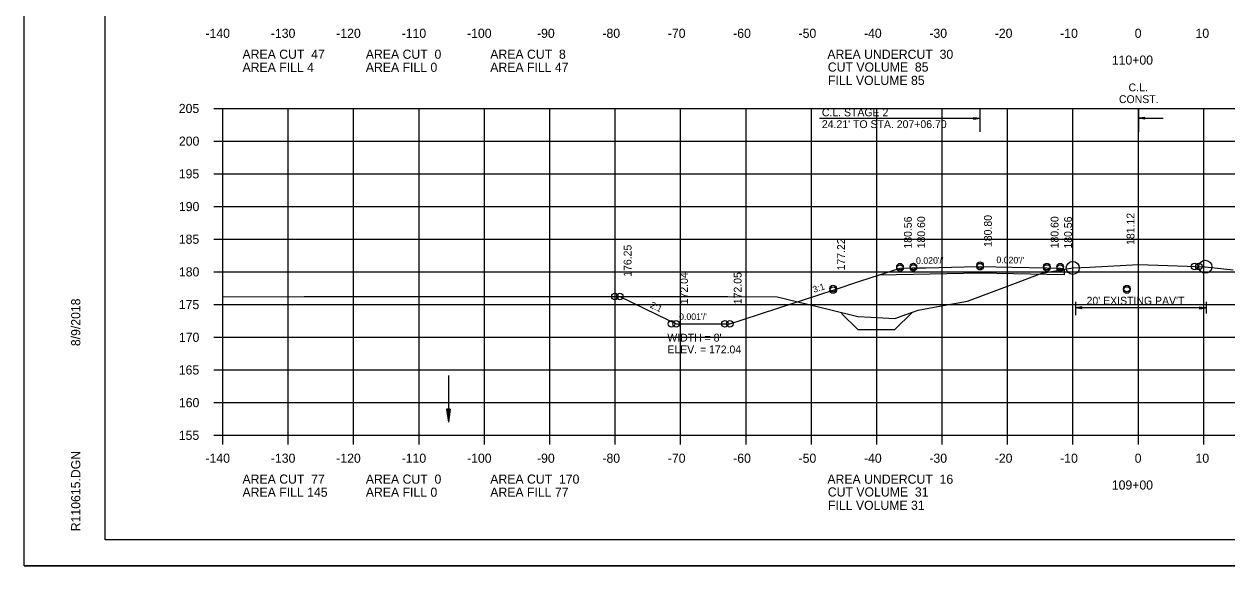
# Model space of a CAD drawing. Extents: x 1372132 to 1372465, y 380083 to 381790.
# Drawn here: x 1372131.6 to 1372315.6, y 381363.5 to 381446.4 of the extents above; entities that cross this region are included whole.
import ezdxf

# ---------------------------------------------------------------- set-up
doc = ezdxf.new("R2010")
doc.units = 0
for name, color, linetype in [('R_Alt Surface', 7, 'Continuous'), ('R_Axis', 7, 'Continuous'), ('R_Axis Annot', 7, 'Continuous'), ('R_Border', 7, 'Continuous'), ('R_Dimension', 7, 'Continuous'), ('R_Draft', 7, 'Continuous'), ('R_Erosion', 7, 'Continuous'), ('R_Exist Surface', 7, 'Continuous'), ('R_Fin Surface', 7, 'Continuous'), ('R_Grid', 7, 'Continuous'), ('R_No Plot', 7, 'Continuous'), ('R_Xsect Elev', 7, 'Continuous'), ('R_Xsect Slope', 7, 'Continuous')]:
    doc.layers.add(name, color=color, linetype=linetype)

msp = doc.modelspace()

# ---------------------------------------------------------------- linework, layer by layer
at = {"layer": 'R_Alt Surface'}
msp.add_lwpolyline([(1372290.64, 381408.05), (1372288, 381408.1), (1372277.8, 381408.3), (1372267.6, 381408.1), (1372262.3, 381407.99)], dxfattribs=at)
at = {"layer": 'R_Axis'}
for p, q in [((1372160.61, 381433.5), (1372162.01, 381433.5)), ((1372162.01, 381383.5), (1372162.01, 381433.5)), ((1372160.61, 381428.5), (1372162.01, 381428.5)), ((1372160.61, 381423.5), (1372162.01, 381423.5)), ((1372160.61, 381418.5), (1372162.01, 381418.5)), ((1372160.61, 381413.5), (1372162.01, 381413.5)), ((1372160.61, 381408.5), (1372162.01, 381408.5)), ((1372160.61, 381403.5), (1372162.01, 381403.5)), ((1372160.61, 381398.5), (1372162.01, 381398.5)), ((1372160.61, 381393.5), (1372162.01, 381393.5)), ((1372160.61, 381388.5), (1372162.01, 381388.5)), ((1372160.61, 381383.5), (1372162.01, 381383.5)), ((1372162.01, 381383.5), (1372442.01, 381383.5)), ((1372162.01, 381382.1), (1372162.01, 381383.5)), ((1372172.01, 381382.1), (1372172.01, 381383.5)), ((1372182.01, 381382.1), (1372182.01, 381383.5)), ((1372192.01, 381382.1), (1372192.01, 381383.5)), ((1372202.01, 381382.1), (1372202.01, 381383.5)), ((1372212.01, 381382.1), (1372212.01, 381383.5)), ((1372222.01, 381382.1), (1372222.01, 381383.5)), ((1372232.01, 381382.1), (1372232.01, 381383.5)), ((1372242.01, 381382.1), (1372242.01, 381383.5)), ((1372252.01, 381382.1), (1372252.01, 381383.5)), ((1372262.01, 381382.1), (1372262.01, 381383.5)), ((1372272.01, 381382.1), (1372272.01, 381383.5)), ((1372282.01, 381382.1), (1372282.01, 381383.5)), ((1372292.01, 381382.1), (1372292.01, 381383.5)), ((1372302.01, 381382.1), (1372302.01, 381383.5)), ((1372312.01, 381382.1), (1372312.01, 381383.5))]:
    msp.add_line(p, q, dxfattribs=at)
at = {"layer": 'R_Border'}
for p, q in [((1372144.01, 381367.5), (1372144.01, 381572.96)), ((1372144.01, 381367.5), (1372144.01, 381367.5)), ((1372460.19, 381367.5), (1372144.01, 381367.5))]:
    msp.add_line(p, q, dxfattribs=at)
at = {"layer": 'R_Dimension'}
for p, q in [((1372196.19, 381387.52), (1372196.49, 381385.52)), ((1372196.79, 381387.52), (1372196.19, 381387.52)), ((1372196.19, 381387.52), (1372196.49, 381385.52)), ((1372196.79, 381387.52), (1372196.19, 381387.52)), ((1372196.24, 381387.52), (1372196.49, 381385.86)), ((1372196.24, 381387.52), (1372196.49, 381385.86)), ((1372196.29, 381387.52), (1372196.49, 381386.2)), ((1372196.29, 381387.52), (1372196.49, 381386.2)), ((1372196.34, 381387.52), (1372196.49, 381386.54)), ((1372196.34, 381387.52), (1372196.49, 381386.54)), ((1372196.39, 381387.52), (1372196.49, 381386.87)), ((1372196.39, 381387.52), (1372196.49, 381386.87)), ((1372196.44, 381387.52), (1372196.49, 381387.21)), ((1372196.44, 381387.52), (1372196.49, 381387.21)), ((1372196.79, 381387.52), (1372196.49, 381385.52)), ((1372196.59, 381387.52), (1372196.49, 381386.87)), ((1372196.69, 381387.52), (1372196.49, 381386.2)), ((1372196.74, 381387.52), (1372196.49, 381385.86)), ((1372196.64, 381387.52), (1372196.49, 381386.54)), ((1372196.54, 381387.52), (1372196.49, 381387.21)), ((1372196.79, 381387.52), (1372196.49, 381385.52)), ((1372196.59, 381387.52), (1372196.49, 381386.87)), ((1372196.69, 381387.52), (1372196.49, 381386.2)), ((1372196.74, 381387.52), (1372196.49, 381385.86)), ((1372196.64, 381387.52), (1372196.49, 381386.54)), ((1372196.54, 381387.52), (1372196.49, 381387.21))]:
    msp.add_line(p, q, dxfattribs=at)
at = {"layer": 'R_Draft'}
for p, q in [((1372277.8, 381429.91), (1372277.8, 381433.5)), ((1372302.01, 381433.5), (1372302.01, 381429.91)), ((1372253.27, 381431.99), (1372277.8, 381431.99)), ((1372276.8, 381432.14), (1372277.8, 381431.99)), ((1372276.8, 381432.14), (1372276.8, 381431.84)), ((1372276.8, 381432.14), (1372277.8, 381431.99)), ((1372276.8, 381432.14), (1372276.8, 381431.84)), ((1372276.8, 381432.11), (1372277.63, 381431.99)), ((1372276.8, 381432.11), (1372277.63, 381431.99)), ((1372276.8, 381432.09), (1372277.46, 381431.99)), ((1372276.8, 381432.09), (1372277.46, 381431.99)), ((1372276.8, 381432.06), (1372277.3, 381431.99)), ((1372276.8, 381432.06), (1372277.3, 381431.99)), ((1372276.8, 381432.04), (1372277.13, 381431.99)), ((1372276.8, 381432.04), (1372277.13, 381431.99)), ((1372276.8, 381432.01), (1372276.96, 381431.99)), ((1372276.8, 381432.01), (1372276.96, 381431.99)), ((1372276.8, 381431.84), (1372277.8, 381431.99)), ((1372276.8, 381431.94), (1372277.13, 381431.99)), ((1372276.8, 381431.89), (1372277.46, 381431.99)), ((1372276.8, 381431.86), (1372277.63, 381431.99)), ((1372276.8, 381431.92), (1372277.3, 381431.99)), ((1372276.8, 381431.97), (1372276.96, 381431.99)), ((1372276.8, 381431.84), (1372277.8, 381431.99)), ((1372276.8, 381431.94), (1372277.13, 381431.99)), ((1372276.8, 381431.89), (1372277.46, 381431.99)), ((1372276.8, 381431.86), (1372277.63, 381431.99)), ((1372276.8, 381431.92), (1372277.3, 381431.99)), ((1372276.8, 381431.97), (1372276.96, 381431.99)), ((1372303.01, 381432.14), (1372302.01, 381431.99)), ((1372302.01, 381431.99), (1372305.82, 381431.99)), ((1372303.01, 381431.84), (1372302.01, 381431.99)), ((1372303.01, 381432.11), (1372302.18, 381431.99)), ((1372303.01, 381431.86), (1372302.18, 381431.99)), ((1372303.01, 381432.09), (1372302.35, 381431.99)), ((1372303.01, 381431.89), (1372302.35, 381431.99)), ((1372303.01, 381432.06), (1372302.52, 381431.99)), ((1372303.01, 381431.92), (1372302.52, 381431.99)), ((1372303.01, 381432.04), (1372302.69, 381431.99)), ((1372303.01, 381431.94), (1372302.69, 381431.99)), ((1372303.01, 381432.01), (1372302.86, 381431.99)), ((1372303.01, 381431.97), (1372302.86, 381431.99)), ((1372303.01, 381431.84), (1372303.01, 381432.14)), ((1372290.64, 381408.87), (1372290.64, 381408.05)), ((1372292.39, 381403.9), (1372292.39, 381401.88)), ((1372293.39, 381403.13), (1372292.39, 381402.98)), ((1372293.39, 381403.13), (1372292.39, 381402.98)), ((1372312.37, 381402.98), (1372292.39, 381402.98)), ((1372293.39, 381402.83), (1372292.39, 381402.98)), ((1372293.39, 381402.83), (1372292.39, 381402.98)), ((1372292.39, 381402.12), (1372292.39, 381402.12)), ((1372293.39, 381403.1), (1372292.56, 381402.98)), ((1372293.39, 381403.1), (1372292.56, 381402.98)), ((1372293.39, 381402.85), (1372292.56, 381402.98)), ((1372293.39, 381402.85), (1372292.56, 381402.98)), ((1372293.39, 381403.08), (1372292.73, 381402.98)), ((1372293.39, 381403.08), (1372292.73, 381402.98)), ((1372293.39, 381402.88), (1372292.73, 381402.98)), ((1372293.39, 381402.88), (1372292.73, 381402.98)), ((1372293.39, 381403.05), (1372292.9, 381402.98)), ((1372293.39, 381403.05), (1372292.9, 381402.98)), ((1372293.39, 381402.91), (1372292.9, 381402.98)), ((1372293.39, 381402.91), (1372292.9, 381402.98)), ((1372293.39, 381403.03), (1372293.07, 381402.98)), ((1372293.39, 381403.03), (1372293.07, 381402.98)), ((1372293.39, 381402.93), (1372293.07, 381402.98)), ((1372293.39, 381402.93), (1372293.07, 381402.98)), ((1372293.39, 381403), (1372293.23, 381402.98)), ((1372293.39, 381403), (1372293.23, 381402.98)), ((1372293.39, 381402.96), (1372293.23, 381402.98)), ((1372293.39, 381402.96), (1372293.23, 381402.98)), ((1372293.39, 381402.83), (1372293.39, 381403.13)), ((1372293.39, 381402.83), (1372293.39, 381403.13)), ((1372311.37, 381403.13), (1372312.37, 381402.98)), ((1372311.37, 381403.13), (1372311.37, 381402.83)), ((1372311.37, 381403.1), (1372312.2, 381402.98)), ((1372311.37, 381403.08), (1372312.03, 381402.98)), ((1372311.37, 381403.05), (1372311.87, 381402.98)), ((1372311.37, 381403.03), (1372311.7, 381402.98)), ((1372311.37, 381403), (1372311.53, 381402.98)), ((1372311.37, 381402.83), (1372312.37, 381402.98)), ((1372311.37, 381402.93), (1372311.7, 381402.98)), ((1372311.37, 381402.88), (1372312.03, 381402.98)), ((1372311.37, 381402.85), (1372312.2, 381402.98)), ((1372311.37, 381402.91), (1372311.87, 381402.98)), ((1372311.37, 381402.96), (1372311.53, 381402.98)), ((1372312.37, 381403.9), (1372312.37, 381402.12)), ((1372196.49, 381392.66), (1372196.49, 381385.52))]:
    msp.add_line(p, q, dxfattribs=at)
at = {"layer": 'R_Erosion'}
for p, q in [((1372259.09, 381399.67), (1372256.6, 381402.16)), ((1372264.78, 381399.67), (1372267.42, 381402.31)), ((1372259.09, 381399.67), (1372264.78, 381399.67))]:
    msp.add_line(p, q, dxfattribs=at)
at = {"layer": 'R_Exist Surface'}
msp.add_lwpolyline([(1372162.01, 381404.66), (1372174.42, 381404.73), (1372196.12, 381404.72), (1372229.61, 381404.76), (1372239.23, 381404.71), (1372246.77, 381404.68), (1372254.78, 381402.73), (1372259.1, 381401.66), (1372261.08, 381401.58), (1372264.78, 381401.39), (1372266.6, 381402.02), (1372268.36, 381402.63), (1372272.14, 381403.35), (1372275.88, 381404.04), (1372283.63, 381406.92), (1372287.23, 381408.28), (1372290.51, 381408.85), (1372291.98, 381409.1), (1372294.53, 381409.23), (1372302.02, 381409.62), (1372309.49, 381409.37), (1372312.25, 381409.29), (1372316.5, 381408.8)], dxfattribs=at)
at = {"layer": 'R_Fin Surface'}
msp.add_lwpolyline([(1372222.7, 381404.75), (1372228.27, 381402.04), (1372231.33, 381400.54), (1372234.54, 381400.55), (1372239.53, 381400.55), (1372241.41, 381401.17), (1372244.39, 381402.14), (1372251.13, 381404.35), (1372255.35, 381405.72), (1372259.44, 381407.06), (1372265.56, 381409.06), (1372267.43, 381409.1), (1372267.6, 381409.1), (1372268.15, 381409.11), (1372269.5, 381409.14), (1372275.4, 381409.25), (1372277.8, 381409.3), (1372282.66, 381409.21), (1372288, 381409.1), (1372289.64, 381409.07), (1372290.05, 381409.06), (1372290.64, 381408.87)], dxfattribs=at)
at = {"layer": 'R_Grid'}
for p, q in [((1372162.01, 381433.5), (1372442.01, 381433.5)), ((1372162.01, 381383.5), (1372162.01, 381433.5)), ((1372172.01, 381383.5), (1372172.01, 381433.5)), ((1372182.01, 381383.5), (1372182.01, 381433.5)), ((1372192.01, 381383.5), (1372192.01, 381433.5)), ((1372202.01, 381383.5), (1372202.01, 381433.5)), ((1372212.01, 381383.5), (1372212.01, 381433.5)), ((1372222.01, 381383.5), (1372222.01, 381433.5)), ((1372232.01, 381383.5), (1372232.01, 381433.5)), ((1372242.01, 381383.5), (1372242.01, 381433.5)), ((1372252.01, 381383.5), (1372252.01, 381433.5)), ((1372262.01, 381383.5), (1372262.01, 381433.5)), ((1372272.01, 381383.5), (1372272.01, 381433.5)), ((1372282.01, 381383.5), (1372282.01, 381433.5)), ((1372292.01, 381383.5), (1372292.01, 381433.5)), ((1372302.01, 381383.5), (1372302.01, 381433.5)), ((1372312.01, 381383.5), (1372312.01, 381433.5)), ((1372162.01, 381428.5), (1372442.01, 381428.5)), ((1372162.01, 381423.5), (1372442.01, 381423.5)), ((1372162.01, 381418.5), (1372442.01, 381418.5)), ((1372162.01, 381413.5), (1372442.01, 381413.5)), ((1372162.01, 381408.5), (1372442.01, 381408.5)), ((1372162.01, 381403.5), (1372442.01, 381403.5)), ((1372162.01, 381398.5), (1372442.01, 381398.5)), ((1372162.01, 381393.5), (1372442.01, 381393.5)), ((1372162.01, 381388.5), (1372442.01, 381388.5)), ((1372162.01, 381383.5), (1372442.01, 381383.5))]:
    msp.add_line(p, q, dxfattribs=at)
at = {"layer": 'R_No Plot'}
msp.add_line((1372131.61, 381363.52), (1372464.95, 381363.52), dxfattribs=at)
for points in [[(1372131.61, 381576.86), (1372464.95, 381576.86), (1372464.95, 381363.52), (1372131.61, 381363.52)], [(1372377.93, 381572.96), (1372377.93, 381563.08), (1372413.67, 381563.08), (1372413.67, 381560.16), (1372436.87, 381560.16), (1372436.87, 381535.83), (1372460.19, 381535.83), (1372460.19, 381367.5), (1372144.01, 381367.5), (1372144.01, 381572.96)]]:
    msp.add_lwpolyline(points, close=True, dxfattribs=at)
for centre, radius in [((1372265.56, 381409.3), 0.5), ((1372265.56, 381409.06), 0.5), ((1372267.6, 381409.34), 0.5), ((1372267.6, 381409.1), 0.5), ((1372277.8, 381409.54), 0.5), ((1372277.8, 381409.3), 0.5), ((1372288, 381409.34), 0.5), ((1372288, 381409.1), 0.5), ((1372290.05, 381409.3), 0.5), ((1372290.05, 381409.06), 0.5), ((1372291.98, 381409.1), 1), ((1372310.58, 381409.34), 0.5), ((1372311.25, 381409.32), 0.5), ((1372312.25, 381409.29), 1), ((1372255.35, 381405.96), 0.5), ((1372255.35, 381405.72), 0.5), ((1372300.25, 381405.97), 0.5), ((1372300.25, 381405.73), 0.5), ((1372221.96, 381404.75), 0.5), ((1372222.7, 381404.75), 0.5), ((1372230.6, 381400.54), 0.5), ((1372231.33, 381400.54), 0.5), ((1372238.79, 381400.55), 0.5), ((1372239.53, 381400.55), 0.5)]:
    msp.add_circle(centre, radius, dxfattribs=at)
at = {"layer": 'R_Xsect Elev'}
msp.add_line((1372302.01, 381409.62), (1372302.01, 381419.62), dxfattribs=at)

# ---------------------------------------------------------------- texts
at = {"layer": 'R_Axis Annot'}
for s, p in [('-140', (1372159.35, 381444.3)), ('-130', (1372169.35, 381444.3)), ('-120', (1372179.35, 381444.3)), ('-110', (1372189.35, 381444.3)), ('-100', (1372199.35, 381444.3)), ('-90', (1372210.05, 381444.3)), ('-80', (1372220.05, 381444.3)), ('-70', (1372230.05, 381444.3)), ('-60', (1372240.05, 381444.3)), ('-50', (1372250.05, 381444.3)), ('-40', (1372260.05, 381444.3)), ('-30', (1372270.05, 381444.3)), ('-20', (1372280.05, 381444.3)), ('-10', (1372290.05, 381444.3)), ('0', (1372301.45, 381444.3)), ('10', (1372310.75, 381444.3)), ('AREA CUT  47', (1372165.01, 381441.1)), ('AREA CUT  0', (1372183.87, 381441.1)), ('AREA CUT  8', (1372202.9, 381441.1)), ('AREA UNDERCUT  30', (1372254.45, 381441.09)), ('110+00', (1372297.95, 381440.2)), ('AREA FILL 4', (1372165.01, 381439.1)), ('AREA FILL 0', (1372183.87, 381439.1)), ('AREA FILL 47', (1372202.9, 381439.1)), ('CUT VOLUME  85', (1372254.52, 381439.14)), ('FILL VOLUME 85', (1372254.55, 381437.1)), ('205', (1372155.27, 381432.8)), ('200', (1372155.29, 381427.8)), ('195', (1372155.27, 381422.8)), ('190', (1372155.29, 381417.8)), ('185', (1372155.27, 381412.8)), ('180', (1372155.29, 381407.8)), ('175', (1372155.27, 381402.8)), ('170', (1372155.29, 381397.8)), ('165', (1372155.27, 381392.8)), ('160', (1372155.29, 381387.8)), ('155', (1372155.27, 381382.8)), ('-140', (1372159.35, 381379.3)), ('-130', (1372169.35, 381379.3)), ('-120', (1372179.35, 381379.3)), ('-110', (1372189.35, 381379.3)), ('-100', (1372199.35, 381379.3)), ('-90', (1372210.05, 381379.3)), ('-80', (1372220.05, 381379.3)), ('-70', (1372230.05, 381379.3)), ('-60', (1372240.05, 381379.3)), ('-50', (1372250.05, 381379.3)), ('-40', (1372260.05, 381379.3)), ('-30', (1372270.05, 381379.3)), ('-20', (1372280.05, 381379.3)), ('-10', (1372290.05, 381379.3)), ('0', (1372301.45, 381379.3)), ('10', (1372310.75, 381379.3)), ('AREA CUT  77', (1372165.01, 381376.1)), ('AREA CUT  0', (1372183.87, 381376.1)), ('AREA CUT  170', (1372202.9, 381376.1)), ('AREA UNDERCUT  16', (1372254.45, 381376.09)), ('109+00', (1372297.95, 381375.2)), ('AREA FILL 145', (1372165.01, 381374.1)), ('AREA FILL 0', (1372183.87, 381374.1)), ('AREA FILL 77', (1372202.9, 381374.1)), ('CUT VOLUME  31', (1372254.52, 381374.14)), ('FILL VOLUME 31', (1372254.55, 381372.1))]:
    msp.add_text(s, height=1.4, dxfattribs=at).set_placement(p)
at = {"layer": 'R_Border'}
for s, p in [('8/9/2018', (1372140.21, 381397.14)), ('R110615.DGN', (1372140.21, 381368.83))]:
    msp.add_text(s, height=1.4, rotation=90, dxfattribs=at).set_placement(p)
at = {"layer": 'R_Dimension'}
for s, p in [("WIDTH = 8'", (1372229.98, 381397.84)), ('ELEV. = 172.04', (1372229.98, 381396.04))]:
    msp.add_text(s, height=1.2, dxfattribs=at).set_placement(p)
at = {"layer": 'R_Draft'}
for s, p in [('C.L. ', (1372300.51, 381436.12)), ('CONST. ', (1372299.04, 381434.32)), ('C.L. STAGE 2', (1372253.61, 381432.3)), ("24.21' TO STA. 207+06.70", (1372253.61, 381430.5)), ("20' EXISTING PAV'T", (1372294.09, 381403.49))]:
    msp.add_text(s, height=1.2, rotation=360, dxfattribs=at).set_placement(p)
at = {"layer": 'R_Xsect Elev'}
for s, p in [('180.56', (1372267.36, 381412.06)), ('180.60', (1372269.4, 381412.1)), ('180.80', (1372279.6, 381412.3)), ('180.60', (1372289.8, 381412.1)), ('180.56', (1372291.85, 381412.06)), ('181.12', (1372301.41, 381412.62)), ('177.22', (1372257.15, 381408.72)), ('176.25', (1372224.5, 381407.75)), ('172.04', (1372233.13, 381403.54)), ('172.05', (1372241.33, 381403.55))]:
    msp.add_text(s, height=1.2, rotation=90, dxfattribs=at).set_placement(p)
at = {"layer": 'R_Xsect Slope'}
for s, rotation, p in [("0.020'/'", 1.1284, (1372268.02, 381409.71)), ("0.020'/'", 358.8827, (1372280.29, 381409.85)), ('3:1', 18.0943, (1372252.39, 381405.28)), ('2:1', 334.0315, (1372227.23, 381403.1)), ("0.001'/'", 0.0708, (1372231.78, 381401.14))]:
    msp.add_text(s, height=1, rotation=rotation, dxfattribs=at).set_placement(p)

doc.saveas('drawing.dxf')
